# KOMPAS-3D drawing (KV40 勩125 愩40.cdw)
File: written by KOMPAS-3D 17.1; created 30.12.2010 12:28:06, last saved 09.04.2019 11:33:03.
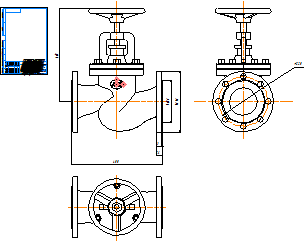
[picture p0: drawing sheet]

Title block, sheet 1: name: KV 40 Ду125; material: Внимание! Данный продукт является объектом авторского права ООО «Торговый Дом АДЛ». / Запрещается изменение, копирование, распространение / (в том числе путем копирования на другие сайты и ресурсы в Интернете) / или любое иное использование информации и объектов без предварительного / согласия правообладателя (ООО «Торговый Дом АДЛ»).; scale: 1:1; sheets: 1; organisation: ООО "Торговый дом АДЛ"; sheet format: A4; stored path: \\adlc.lan\data\АДЛ_ПКД\3D-модели\ADL production\Вентили ГРАНВЕНТ\KV40\KOMPAS 2D\KV 40 Ду125.cdw

Views: Проекционный вид 3, Спереди 1, Проекционный вид 2
Dimensions and other numbers on the sheet: 188; 270; 3; 26; 400; 410; 220; 1:1; 1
